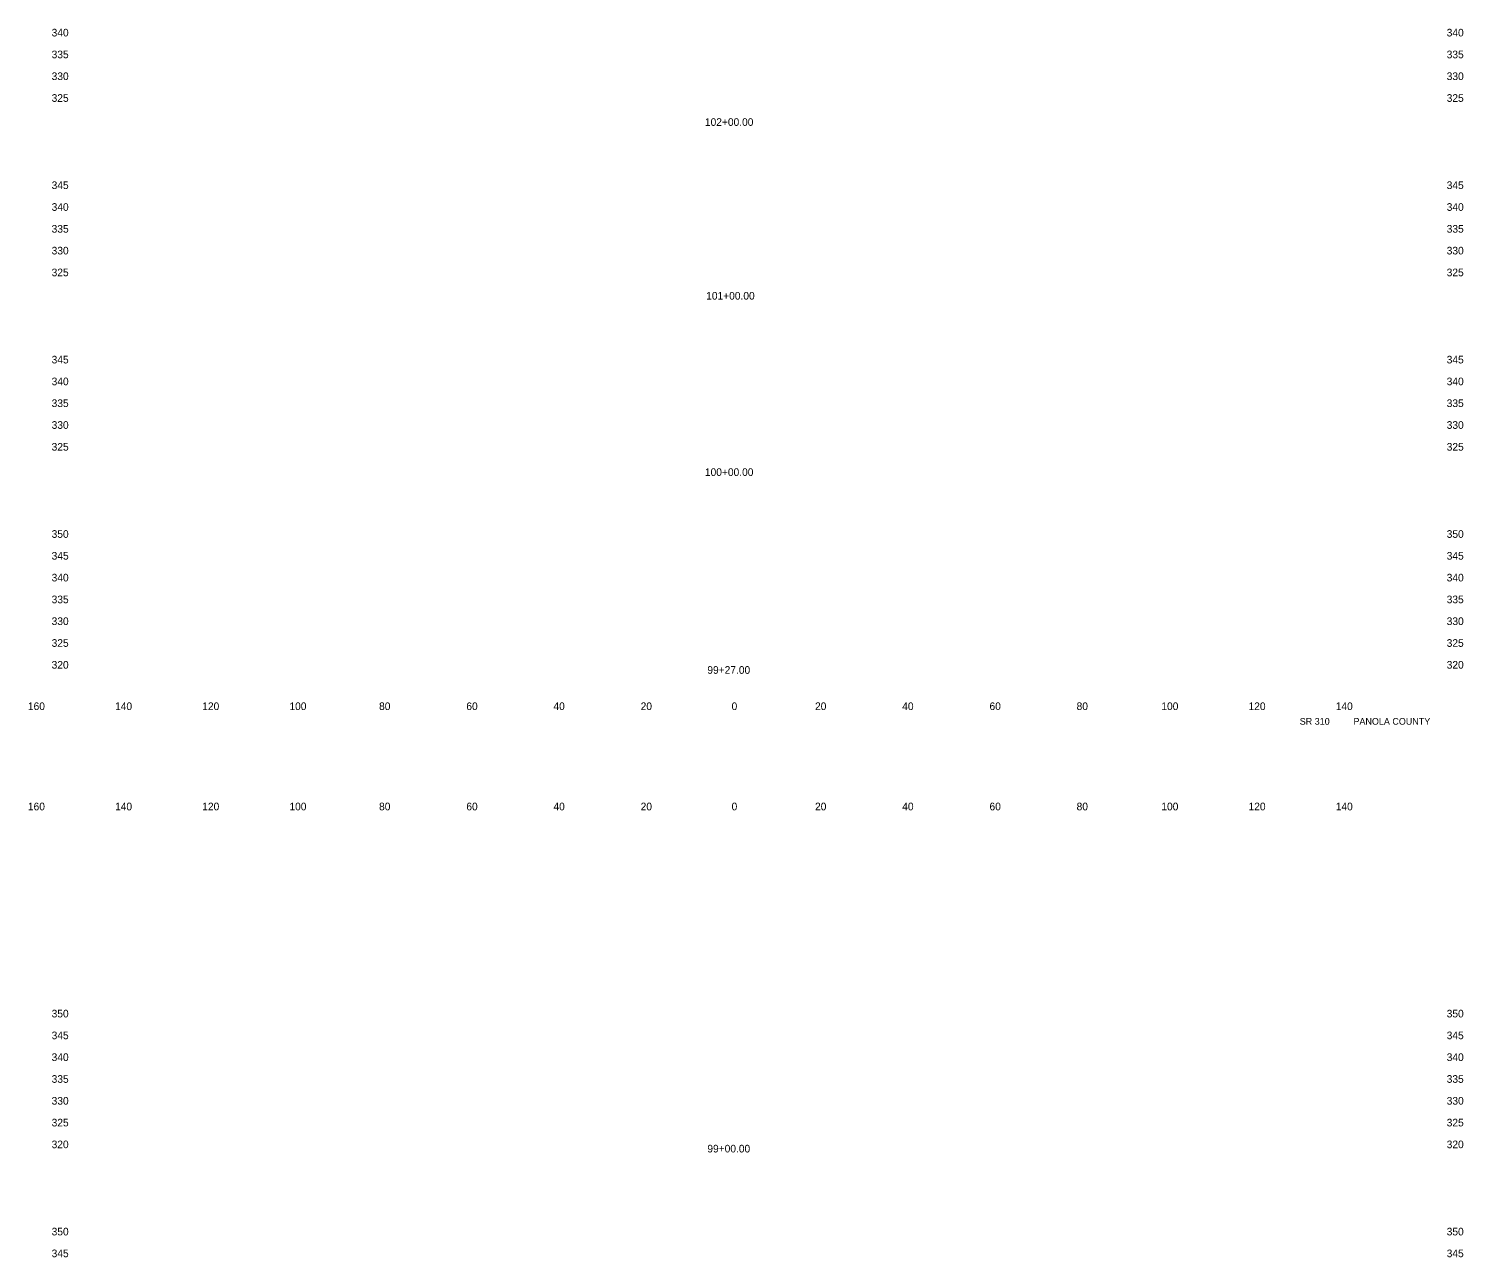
# Model space of a CAD drawing. Extents: x 21481 to 21810, y 6485 to 11067.
# Drawn here: x 21480.9 to 21809.9, y 7052.7 to 7334.5 of the extents above; entities that cross this region are included whole.
import ezdxf

# ---------------------------------------------------------------- set-up
doc = ezdxf.new("R2010")
doc.units = 0
for name, color, linetype in [('62', 7, 'Continuous'), ('XS_CELL', 7, 'Continuous'), ('XS_P_TX_DCH', 7, 'Continuous'), ('XS_P_TX_FS_BS', 7, 'Continuous')]:
    doc.layers.add(name, color=color, linetype=linetype)

msp = doc.modelspace()

# ---------------------------------------------------------------- texts
at = {"layer": '62'}
for s, p in [('  160  ', (21479.4, 7178.21)), ('  140  ', (21499.39, 7178.21)), ('  120  ', (21519.39, 7178.21)), ('  100  ', (21539.39, 7178.21)), ('  80  ', (21559.95, 7178.21)), ('  60  ', (21579.97, 7178.21)), ('  40  ', (21599.95, 7178.21)), ('  20  ', (21619.95, 7178.21)), ('  0  ', (21640.81, 7178.21)), ('  0  ', (21640.81, 7178.21)), ('  20  ', (21659.95, 7178.21)), ('  40  ', (21679.95, 7178.21)), ('  60  ', (21699.97, 7178.21)), ('  80  ', (21719.95, 7178.21)), ('  100  ', (21739.39, 7178.21)), ('  120  ', (21759.39, 7178.21)), ('  140  ', (21779.39, 7178.21)), ('  160  ', (21479.4, 7155.21)), ('  140  ', (21499.39, 7155.21)), ('  120  ', (21519.39, 7155.21)), ('  100  ', (21539.39, 7155.21)), ('  80  ', (21559.95, 7155.21)), ('  60  ', (21579.97, 7155.21)), ('  40  ', (21599.95, 7155.21)), ('  20  ', (21619.95, 7155.21)), ('  0  ', (21640.81, 7155.21)), ('  0  ', (21640.81, 7155.21)), ('  20  ', (21659.95, 7155.21)), ('  40  ', (21679.95, 7155.21)), ('  60  ', (21699.97, 7155.21)), ('  80  ', (21719.95, 7155.21)), ('  100  ', (21739.39, 7155.21)), ('  120  ', (21759.39, 7155.21)), ('  140  ', (21779.39, 7155.21))]:
    msp.add_text(s, height=1.75, dxfattribs=at).set_placement(p)
at = {"layer": 'XS_CELL'}
for s, p in [('  340  ', (21484.84, 7332.71)), ('  340  ', (21804.84, 7332.71)), ('  335  ', (21484.84, 7327.71)), ('  335  ', (21804.84, 7327.71)), ('  330  ', (21484.84, 7322.71)), ('  330  ', (21804.84, 7322.71)), ('  325  ', (21484.84, 7317.71)), ('  325  ', (21804.84, 7317.71)), ('  345  ', (21484.84, 7297.71)), ('  345  ', (21804.84, 7297.71)), ('  340  ', (21484.84, 7292.71)), ('  340  ', (21804.84, 7292.71)), ('  335  ', (21484.84, 7287.71)), ('  335  ', (21804.84, 7287.71)), ('  330  ', (21484.84, 7282.71)), ('  330  ', (21804.84, 7282.71)), ('  325  ', (21484.84, 7277.71)), ('  325  ', (21804.84, 7277.71)), ('  345  ', (21484.84, 7257.71)), ('  345  ', (21804.84, 7257.71)), ('  340  ', (21484.84, 7252.71)), ('  340  ', (21804.84, 7252.71)), ('  335  ', (21484.84, 7247.71)), ('  335  ', (21804.84, 7247.71)), ('  330  ', (21484.84, 7242.71)), ('  330  ', (21804.84, 7242.71)), ('  325  ', (21484.84, 7237.71)), ('  325  ', (21804.84, 7237.71)), ('  350  ', (21484.84, 7217.71)), ('  350  ', (21804.84, 7217.71)), ('  345  ', (21484.84, 7212.71)), ('  345  ', (21804.84, 7212.71)), ('  340  ', (21484.84, 7207.71)), ('  340  ', (21804.84, 7207.71)), ('  335  ', (21484.84, 7202.71)), ('  335  ', (21804.84, 7202.71)), ('  330  ', (21484.84, 7197.71)), ('  330  ', (21804.84, 7197.71)), ('  325  ', (21484.84, 7192.71)), ('  325  ', (21804.84, 7192.71)), ('  320  ', (21484.84, 7187.71)), ('  320  ', (21804.84, 7187.71)), ('  350  ', (21484.84, 7107.71)), ('  350  ', (21804.84, 7107.71)), ('  345  ', (21484.84, 7102.71)), ('  345  ', (21804.84, 7102.71)), ('  340  ', (21484.84, 7097.71)), ('  340  ', (21804.84, 7097.71)), ('  335  ', (21484.84, 7092.71)), ('  335  ', (21804.84, 7092.71)), ('  330  ', (21484.84, 7087.71)), ('  330  ', (21804.84, 7087.71)), ('  325  ', (21484.84, 7082.71)), ('  325  ', (21804.84, 7082.71)), ('  320  ', (21484.84, 7077.71)), ('  320  ', (21804.84, 7077.71)), ('  350  ', (21484.84, 7057.71)), ('  350  ', (21804.84, 7057.71)), ('  345  ', (21484.84, 7052.71)), ('  345  ', (21804.84, 7052.71))]:
    msp.add_text(s, height=1.75, dxfattribs=at).set_placement(p)
at = {"layer": 'XS_P_TX_DCH'}
for s, p in [('  102+00.00  ', (21634.69, 7312.2)), ('  101+00.00  ', (21634.98, 7272.35)), ('  100+00.00  ', (21634.69, 7231.9)), ('  99+27.00  ', (21635.25, 7186.53)), ('  99+00.00  ', (21635.25, 7076.74))]:
    msp.add_text(s, height=1.75, dxfattribs=at).set_placement(p)
at = {"layer": 'XS_P_TX_FS_BS'}
for s, p in [('SR 310', (21772.43, 7174.84)), ('SR 310', (21772.43, 7174.84)), ('SR 310', (21772.43, 7174.84)), ('PANOLA COUNTY', (21784.75, 7174.84)), ('PANOLA COUNTY', (21784.75, 7174.84)), ('PANOLA COUNTY', (21784.75, 7174.84))]:
    msp.add_text(s, height=1.54, dxfattribs=at).set_placement(p)

doc.saveas('drawing.dxf')
